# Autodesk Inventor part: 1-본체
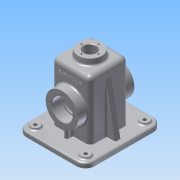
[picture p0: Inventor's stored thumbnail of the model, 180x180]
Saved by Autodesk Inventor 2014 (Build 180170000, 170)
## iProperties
Created: 2016-06
Part Number: 1-본체
Material: 알루미늄 6061
Document SubType Name: Modeling
Designer: Administrator
Density: 2.71 g/cm^3
Appearance: 알루미늄 - 평지
Mass: 807.297 g
Surface Area: 910.695 cm^2
Volume: 297.895 cm^3
Author: Administrator
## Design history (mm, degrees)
sketch "스케치1"
  geometry: L1 (57.5, -65)-(-57.5, -65); L2 (-57.5, -65)-(-57.5, 65); L3 (-57.5, 65)-(57.5, 65); L4 (57.5, 65)-(57.5, -65); L5 (57.5, -65)-(-57.5, 65); L6 (-57.5, -65)-(57.5, 65); 3 further points
  constraints: 12 end point, 3 midpoint, 2 parallel, 1 coincident, 1 horizontal, 1 perpendicular
  dimensions: "d0" = 115 distance of L2.end L3.end; "d1" = 130 distance of L1.end L2.end
extrude "돌출1" new body sketch "스케치1" distance "d2" = 8; taper "d3" = 0 deg
sketch "스케치2"
  geometry: L1 (52.5, 60)-(-52.5, 60); L2 (-52.5, 60)-(-52.5, -60); L3 (-52.5, -60)-(52.5, -60); L4 (52.5, -60)-(52.5, 60); L5 (52.5, 60)-(-52.5, -60); L6 (-52.5, 60)-(52.5, -60); 1 further point
  constraints: 12 end point, 2 midpoint, 2 parallel, 1 horizontal, 1 perpendicular
  dimensions: "d4" = 105 distance of L3.end L2.end; "d5" = 120 distance of L2.end L1.end
extrude "돌출2" join sketch "스케치2" distance "d6" = 2; taper "d7" = 0 deg
fillet "모깎기1" dims "d8" = 15, "d9" = 10
sketch "스케치3"
  geometry: L1 (32.5, 32.5)-(-32.5, 32.5); L2 (-32.5, 32.5)-(-32.5, -32.5); L3 (-32.5, -32.5)-(32.5, -32.5); L4 (32.5, -32.5)-(32.5, 32.5); L5 (32.5, 32.5)-(-32.5, -32.5); L6 (-32.5, 32.5)-(32.5, -32.5); 1 further point
  constraints: 12 end point, 2 midpoint, 2 parallel, 1 horizontal, 1 perpendicular
  dimensions: "d10" = 65 distance of L3.end L2.end; "d11" = 65 distance of L2.end L1.end
extrude "돌출3" join sketch "스케치3" distance "d12" = 100; taper "d13" = 0 deg
node "작업 평면1"
sketch "스케치5"
  geometry: C1 r 20 at (0, 0); 1 further point
  constraints: 1 centre point, 1 coincident
  dimensions: "d16" = 40 diameter of C1
extrude "돌출4" join sketch "스케치5" distance "d17" = 10; taper "d18" = 5 deg
sketch "스케치7"
  geometry: L1 (27.5, 27.5)-(-27.5, 27.5); L2 (-27.5, 27.5)-(-27.5, -27.5); L3 (-27.5, -27.5)-(27.5, -27.5); L4 (27.5, -27.5)-(27.5, 27.5); L5 (27.5, 27.5)-(-27.5, -27.5); L6 (-27.5, 27.5)-(27.5, -27.5); 3 further points
  constraints: 12 end point, 3 midpoint, 2 parallel, 1 coincident, 1 horizontal, 1 perpendicular
  dimensions: "d19" = 55 distance of L3.end L2.end; "d20" = 55 distance of L2.end L1.end
extrude "돌출5" cut sketch "스케치7" distance "d21" = 105; taper "d22" = 0 deg
sketch "스케치9"
  geometry: C1 r 7.5 at (-42.5, 50); A1 r 15 centre (-42.5, 50) between (-42.5, 65) and (-57.5, 50) reference; 1 further point
  constraints: 1 centre point, 1 coincident
  dimensions: "d23" = 15 diameter of C1
extrude "돌출6" join sketch "스케치9" distance "d24" = 3; taper "d25" = 0 deg
sketch "스케치10"
  geometry: C1 r 7.5 at (0, 0) reference; C2 r 3 at (0, 0); 1 further point
  constraints: 1 centre point, 1 coincident
  dimensions: "d26" = 6 diameter of C2
extrude "돌출7" cut sketch "스케치10" distance "d27" = 20; taper "d28" = 0 deg
fillet "모깎기2" dims "d29" = 3
fillet "모깎기3" dims "d37" = 3, "d73" = 3, "d74" = 3
sketch "스케치12"
  geometry: L1 (0, 100)-(65, 100) reference; L2 (85, -10)-(75, -10) reference; C1 r 27.5 at (32.5, 45); 2 further points
  constraints: 1 centre point, 1 midpoint, 1 vertical alignment
  dimensions: "d40" = 55 diameter of C1; "d41" = 55 distance from line of L2 C1.centre
extrude "돌출8" join sketch "스케치12" distance "d42" = 15; taper "d43" = 0 deg
hole "구멍1" diameter "d46" = 30; stored, may be unused: countersink angle "d50" = 90 deg, drill point angle "d52" = 118 deg; dims "d44" = 10, "d45" = 10, "d47" = 6, "d48" = 35, "d49" = 17, "d51" = 20
sketch "스케치14"
  geometry: C1 r 17.5 at (0, 0) reference; 2 further points
  constraints: 1 vertical alignment
  dimensions: "d53" = 21 distance of C1.centre point (0, 21)
hole "구멍2" sketch "스케치14" at (0, 21) diameter "d54" = 3.242; stored, may be unused: countersink angle "d58" = 90 deg, drill point angle "d60" = 118 deg; dims "d55" = 8, "d56" = 35, "d57" = 17, "d59" = 10
chamfer "모따기1" distance "d64" = 1; stored, may be unused: second distance "d65" = 2, angle "d66" = 45 deg
fillet "모깎기4" dims "d67" = 0.3
fillet "모깎기5" dims "d68" = 8
fillet "모깎기6" dims "d69" = 3
fillet "모깎기7" dims "d70" = 8, "d71" = 3
fillet "모깎기8" dims "d72" = 8
sketch "스케치15"
  geometry: C1 r 20 at (0, 0) reference; C2 r 10.5 at (0, 0)
  constraints: 1 centre point, 1 coincident
  dimensions: "d75" = 21 diameter of C2
extrude "돌출9" cut sketch "스케치15" distance "d76" = 30; taper "d77" = 0 deg
sketch "스케치16"
  geometry: C1 r 10.5 at (0, 0) reference; 1 further point
  constraints: 1 vertical alignment
  dimensions: "d78" = 14.5 distance of C1.centre point (0, 14.5)
hole "구멍3" sketch "스케치16" at (0, 14.5) diameter "d79" = 2.459; stored, may be unused: countersink angle "d83" = 90 deg, drill point angle "d85" = 118 deg; dims "d80" = 7, "d81" = 35, "d82" = 17, "d84" = 9
sketch "스케치18"
  geometry: L1 (-27.5, 100)-(-27.5, -2) reference; L2 (-27.5, -2)-(-52.5, -2) reference; L3 (-52.5, -2)-(-52.5, 0) reference; L4 (-52.5, 0)-(-57.5, 0) reference; L5 (-57.5, 0)-(-57.5, 8) reference; L6 (-57.5, 8)-(-32.5, 8) reference; L7 (-32.5, 8)-(-32.5, 100) reference; L8 (-24.5, 108)-(-23.624, 108) reference; L9 (-20.635, 110.739)-(-20, 118) reference; L10 (-20, 118)-(-15.73, 118) reference; L11 (-15.73, 118)-(-15.73, 109) reference; L12 (-15.73, 109)-(-14.5, 108.261) reference; L13 (-14.5, 108.261)-(-13.271, 109) reference; L14 (-13.271, 109)-(-13.271, 118) reference; L15 (-13.271, 118)-(-10.5, 118) reference; L16 (-10.5, 118)-(-10.5, 103) reference; L17 (-10.5, 103)-(-24.5, 103) reference; L18 (24.5, 103)-(10.5, 103) reference; L19 (10.5, 103)-(10.5, 118) reference; L20 (10.5, 118)-(13.271, 118) reference; L21 (13.271, 118)-(13.271, 109) reference; L22 (13.271, 109)-(14.5, 108.261) reference; L23 (14.5, 108.261)-(15.73, 109) reference; L24 (15.73, 109)-(15.73, 118) reference; L25 (15.73, 118)-(20, 118) reference; L26 (20, 118)-(20.635, 110.739) reference; L27 (23.624, 108)-(24.5, 108) reference; L28 (32.5, 100)-(32.5, 8) reference; L29 (32.5, 8)-(57.5, 8) reference; L30 (57.5, 8)-(57.5, 0) reference; L31 (57.5, 0)-(52.5, 0) reference; L32 (52.5, 0)-(52.5, -2) reference; L33 (52.5, -2)-(27.5, -2) reference; L34 (27.5, -2)-(27.5, 100) reference; L35 (-32, 8)-(-53, 8) reference; L36 (-47.5, 8)-(-32.5, 93.069); L37 (-32.5, 8)-(-32.5, 100) reference; A1 r 3 centre (-24.5, 100) between (-24.5, 103) and (-27.5, 100) reference; A2 r 8 centre (-24.5, 100) between (-24.5, 108) and (-32.5, 100) reference; A3 r 3 centre (-23.624, 111) between (-23.624, 108) and (-20.635, 110.739) reference; A4 r 3 centre (24.5, 100) between (27.5, 100) and (24.5, 103) reference; A5 r 3 centre (23.624, 111) between (20.635, 110.739) and (23.624, 108) reference; A6 r 8 centre (24.5, 100) between (32.5, 100) and (24.5, 108) reference; 1 further point
  constraints: 2 end point, 2 point on line
  dimensions: "d95" = 10 distance from line of L5 L36.start; "d96" = 10 deg angle of L5 L36
extrude "돌출11" join sketch "스케치18" stored distance "d97" = 10; taper "d98" = 0 deg
sketch "스케치19"
  geometry: L1 (24.5, 103)-(10.5, 103) reference; L2 (10.5, 103)-(10.5, 118) reference; L3 (10.5, 118)-(13.271, 118) reference; L4 (13.271, 118)-(13.271, 109) reference; L5 (13.271, 109)-(14.5, 108.261) reference; L6 (14.5, 108.261)-(15.73, 109) reference; L7 (15.73, 109)-(15.73, 118) reference; L8 (15.73, 118)-(20, 118) reference; L9 (20, 118)-(20.635, 110.739) reference; L10 (23.624, 108)-(24.5, 108) reference; L11 (32.5, 100)-(32.5, 83.5) reference; L12 (35.5, 80.5)-(47.5, 80.5) reference; L13 (47.5, 80.5)-(47.5, 75.621) reference; L14 (47.5, 75.621)-(37.5, 75.621) reference; L15 (37.5, 75.621)-(36.526, 74) reference; L16 (36.526, 74)-(37.5, 72.379) reference; L17 (37.5, 72.379)-(47.5, 72.379) reference; L18 (47.5, 72.379)-(47.5, 71.5) reference; L19 (47.5, 71.5)-(46.5, 70.5) reference; L20 (46.5, 70.5)-(30.8, 70.5) reference; L21 (30.5, 70.2)-(30.5, 68) reference; L22 (30.5, 68)-(27.5, 68) reference; L23 (27.5, 68)-(27.5, 100) reference; L24 (-27.5, 100)-(-27.5, 68) reference; L25 (-27.5, 68)-(-30.5, 68) reference; L26 (-30.5, 68)-(-30.5, 70.2) reference; L27 (-30.8, 70.5)-(-46.5, 70.5) reference; L28 (-46.5, 70.5)-(-47.5, 71.5) reference; L29 (-47.5, 71.5)-(-47.5, 72.379) reference; L30 (-47.5, 72.379)-(-37.5, 72.379) reference; L31 (-37.5, 72.379)-(-36.526, 74) reference; L32 (-36.526, 74)-(-37.5, 75.621) reference; L33 (-37.5, 75.621)-(-47.5, 75.621) reference; L34 (-47.5, 75.621)-(-47.5, 80.5) reference; L35 (-47.5, 80.5)-(-35.5, 80.5) reference; L36 (-32.5, 83.5)-(-32.5, 100) reference; L37 (-24.5, 108)-(-23.624, 108) reference; L38 (-20.635, 110.739)-(-20, 118) reference; L39 (-20, 118)-(-15.73, 118) reference; L40 (-15.73, 118)-(-15.73, 109) reference; L41 (-15.73, 109)-(-14.5, 108.261) reference; L42 (-14.5, 108.261)-(-13.271, 109) reference; L43 (-13.271, 109)-(-13.271, 118) reference; L44 (-13.271, 118)-(-10.5, 118) reference; L45 (-10.5, 118)-(-10.5, 103) reference; L46 (-10.5, 103)-(-24.5, 103) reference; L47 (-60, -2)-(-60, 0) reference; L48 (-60, 0)-(-65, 0) reference; L49 (-65, 0)-(-65, 8) reference; L50 (-65, 8)-(-32.5, 8) reference; L51 (-32.5, 8)-(-32.5, 22.5) reference; L52 (-35.5, 25.5)-(-47.5, 25.5) reference; L53 (-47.5, 25.5)-(-47.5, 30.379) reference; L54 (-47.5, 30.379)-(-37.5, 30.379) reference; L55 (-37.5, 30.379)-(-36.526, 32) reference; L56 (-36.526, 32)-(-37.5, 33.621) reference; L57 (-37.5, 33.621)-(-47.5, 33.621) reference; L58 (-47.5, 33.621)-(-47.5, 34.5) reference; L59 (-47.5, 34.5)-(-46.5, 35.5) reference; L60 (-46.5, 35.5)-(-30.8, 35.5) reference; L61 (-30.5, 35.8)-(-30.5, 38) reference; L62 (-30.5, 38)-(-27.5, 38) reference; L63 (-27.5, 38)-(-27.5, -2) reference; L64 (-27.5, -2)-(-60, -2) reference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; A1 r 3 centre (24.5, 100) between (27.5, 100) and (24.5, 103) reference; A2 r 3 centre (23.624, 111) between (20.635, 110.739) and (23.624, 108) reference; A3 r 8 centre (24.5, 100) between (32.5, 100) and (24.5, 108) reference; A4 r 3 centre (35.5, 83.5) between (32.5, 83.5) and (35.5, 80.5) reference; A5 r 0.3 centre (30.8, 70.2) between (30.8, 70.5) and (30.5, 70.2) reference; A6 r 3 centre (-24.5, 100) between (-24.5, 103) and (-27.5, 100) reference; A7 r 0.3 centre (-30.8, 70.2) between (-30.5, 70.2) and (-30.8, 70.5) reference; A8 r 3 centre (-35.5, 83.5) between (-35.5, 80.5) and (-32.5, 83.5) reference; A9 r 8 centre (-24.5, 100) between (-24.5, 108) and (-32.5, 100) reference; A10 r 3 centre (-23.624, 111) between (-23.624, 108) and (-20.635, 110.739) reference; A11 r 3 centre (-35.5, 22.5) between (-32.5, 22.5) and (-35.5, 25.5) reference; A12 r 0.3 centre (-30.8, 35.8) between (-30.8, 35.5) and (-30.5, 35.8) reference; A13 r 0.3 centre (30.8, 35.8) between (30.5, 35.8) and (30.8, 35.5) reference; A14 r 3 centre (35.5, 22.5) between (35.5, 25.5) and (32.5, 22.5) reference; 1 further point
  constraints: 8 end point, 2 parallel, 1 collinear, 1 perpendicular, 1 point on line
  dimensions: "d99" = 20 distance of L84.end L50.end; "d101" = 15 distance between parallel lines of L63 L83
extrude "돌출12" join sketch "스케치19" stored distance "d102" = 6; taper "d103" = 0 deg
fillet "모깎기9" dims "d111" = 2
fillet "모깎기12" dims "d107" = 3
sketch "스케치21"
  geometry: L1 (20, 65)-(-20, 65) reference; A1 r 30.5 centre (0, 0) between (24.5, 18.166) and (-24.5, 18.166) reference; 2 further points
  constraints: 1 vertical alignment, 1 other
  dimensions: "d108" = 26 distance from line of point (0, 39) L1
feature "엠보싱1" sketch "스케치21" dims "d109" = 0.5, "d110" = 0
fillet "모깎기13" dims "d112" = 3
fillet "모깎기14" dims "d113" = 3
chamfer "모따기2" distance "d117" = 1; stored, may be unused: second distance "d118" = 2, angle "d119" = 45 deg
fillet "모깎기19" dims "d121" = 3
fillet "모깎기20" dims "d122" = 3
fillet "모깎기21" dims "d123" = 1
node "솔리드1"
pattern_linear "직사각형 패턴1" dims "d35" = 85
pattern_circular "원형 패턴1" dims angle "d62" = 360 deg
mirror "대칭1"
pattern_circular "원형 패턴2" dims angle "d87" = 360 deg
mirror "대칭3"
mirror "대칭4"
node "절단 모서리 투영2"
node "절단 모서리 투영3"
